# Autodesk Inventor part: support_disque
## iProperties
Created: 2011-01
Part Number: support_disque
Document SubType Name: Modeling
Designer: eric
Density: 1 g/cm^3
Mass: 2.35838 g
Surface Area: 19.8117 cm^2
Volume: 2.35838 cm^3
Author: eric
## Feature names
1. Base1
